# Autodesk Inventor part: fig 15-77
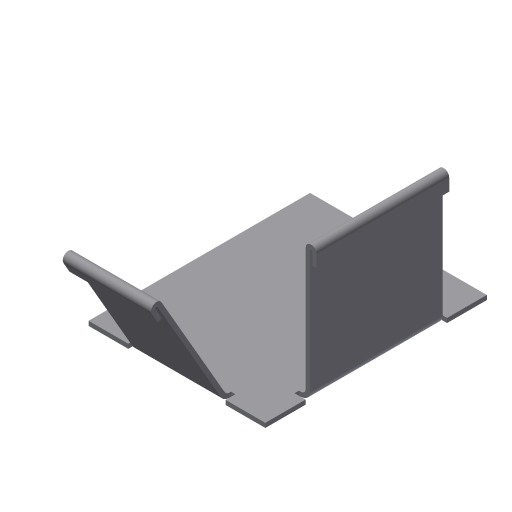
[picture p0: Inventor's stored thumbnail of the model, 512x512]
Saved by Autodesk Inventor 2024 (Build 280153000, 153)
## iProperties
Shininess: 77.0
Angle Display Precision: 2
Document Length Units: 11269
Document Angle Units: 11279
Document Time Units: 11290
Document Mass Units: 11283
Document Length Units Precision: 3
Document Angle Units Precision: 2
Compacted: True
Created: 2002-04
Part Number: fig 15-77
Document SubType Name: Sheet Metal
Density: 1 g/cm^3
Sheet Metal Rule: Default
Material: Generic
Appearance: Default
Density: 0.0
Volumn: 0.0
Area: 0.0
PropertySet Name: Model Information
Control State: 0
Master: False
Checked Out: False
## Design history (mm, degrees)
node "Face1"
  sketch "Sketch1"
    geometry: L1 (-17.882, 11.882)-(2.118, 11.882); L2 (2.118, 11.882)-(2.118, -13.176); L3 (2.118, -13.176)-(-17.882, -13.176); L4 (-17.882, -13.176)-(-17.882, 11.882)
    constraints: 8 end point, 2 parallel, 1 horizontal, 1 perpendicular
    dimensions: "d17" = 20 distance of L2.end L3.end
node "Flange2"
node "Flange3"
feature "Hem8" dims "d82" = 0.5 (= BendReliefWidth), "d83" = 0.25 (= BendReliefDepth), "d84" = 1 (= MinimumRemnant), "d85" = 0.5 (= BendRadius), "d86" = 2 (= 4 x Thickness), "d87" = 0.25 (= 0.5 x Thickness), "d88" = 0.125 (= 0.5 x d87), "d96" = 0.5 (= Thickness), "SeamGap" = 0.01
feature "Hem9" dims "d89" = 0.5 (= BendReliefWidth), "d90" = 0.25 (= BendReliefDepth), "d91" = 1 (= MinimumRemnant), "d92" = 0.5 (= BendRadius), "d93" = 2 (= 4 x Thickness), "d94" = 0.25 (= 0.5 x Thickness), "d95" = 0.125 (= 0.5 x d94), "d96" = 0.5 (= Thickness), "SeamGap" = 0.01
body "Solid1"
face "Plate1" dims "d96" = 0.5 (= Thickness)
sketch "Sketch3"
  geometry: L1 (5, 0)-(20, 0); L2 (20, 0)-(20, 15); L3 (20, 15)-(5, 15); L4 (5, 15)-(5, 0)
  constraints: 8 end point
face "Plate3" dims "d6" = 15, "d7" = 90 deg, "d8" = 0.5 (= BendRadius), "d18" = 5, "d19" = 15, "d96" = 0.5 (= Thickness), "MinimumRemnant" = 1 (= 2 x Thickness), "BendReliefWidth" = 0.5 (= Thickness)
bend "Bend2" dims "d6" = 15, "d7" = 90 deg, "d8" = 0.5 (= BendRadius), "d56" = 0.5 (= BendReliefWidth), "d57" = 0.25 (= BendReliefDepth), "d58" = 1 (= MinimumRemnant), "d96" = 0.5 (= Thickness), "SeamGap" = 0.01, "MinimumRemnant" = 1 (= 2 x Thickness), "BendReliefWidth" = 0.5 (= Thickness), "TransitionRadius" = 0.5 (= BendRadius)
sketch "Sketch6"
  geometry: L1 (15, 0)-(5, 0); L2 (5, 0)-(5, 15); L3 (5, 15)-(15, 15); L4 (15, 15)-(15, 0)
  constraints: 8 end point
face "Plate4" dims "d20" = 5, "d21" = 10, "d23" = 15, "d24" = 60 deg, "d25" = 0.5 (= BendRadius), "d96" = 0.5 (= Thickness), "MinimumRemnant" = 1 (= 2 x Thickness), "BendReliefWidth" = 0.5 (= Thickness)
bend "Bend3" dims "d22" = 0.5 (= BendRadius), "d23" = 15, "d24" = 60 deg, "d25" = 0.5 (= BendRadius), "d59" = 0.5 (= BendReliefWidth), "d60" = 0.25 (= BendReliefDepth), "d61" = 1 (= MinimumRemnant), "d96" = 0.5 (= Thickness), "SeamGap" = 0.01, "MinimumRemnant" = 1 (= 2 x Thickness), "BendReliefWidth" = 0.5 (= Thickness)
sketch "Sketch12"
  geometry: L1 (0.433, 0.25)-(0, 0); L2 (-0.217, -0.125)-(0.471, -1.316); L3 (0.471, -1.316)-(0.038, -1.566); L4 (0.038, -1.566)-(-0.65, -0.375); A1 r 0.125 centre (-0.108, -0.063) between (0, 0) and (-0.217, -0.125); A2 r 0.625 centre (-0.108, -0.063) between (0.433, 0.25) and (-0.65, -0.375)
  constraints: 8 end point, 4 point on circle
sketch "Sketch13"
  geometry: L1 (0.5, 0)-(0, 0); L2 (-0.25, 0)-(-0.25, -1.375); L3 (-0.25, -1.375)-(-0.75, -1.375); L4 (-0.75, -1.375)-(-0.75, 0); A1 r 0.125 centre (-0.125, 0) between (0, 0) and (-0.25, 0); A2 r 0.625 centre (-0.125, 0) between (0.5, 0) and (-0.75, 0)
  constraints: 8 end point, 4 point on circle
other parameters: "Thickness" = 0.5, "BendRadius" = 0.5 (= Thickness), "BendReliefDepth" = 0.25 (= 0.5 x Thickness), "CornerReliefSize" = 2 (= 4 x Thickness), "d0" = 0.5 (= BendRadius), "d5" = 0.5 (= BendRadius), "d26" = 0.5 (= BendRadius), "d30" = 0.5 (= BendRadius), "JacobiRadiusSize" = 0.5 (= Thickness), "GapSize" = 0.5 (= Thickness)
